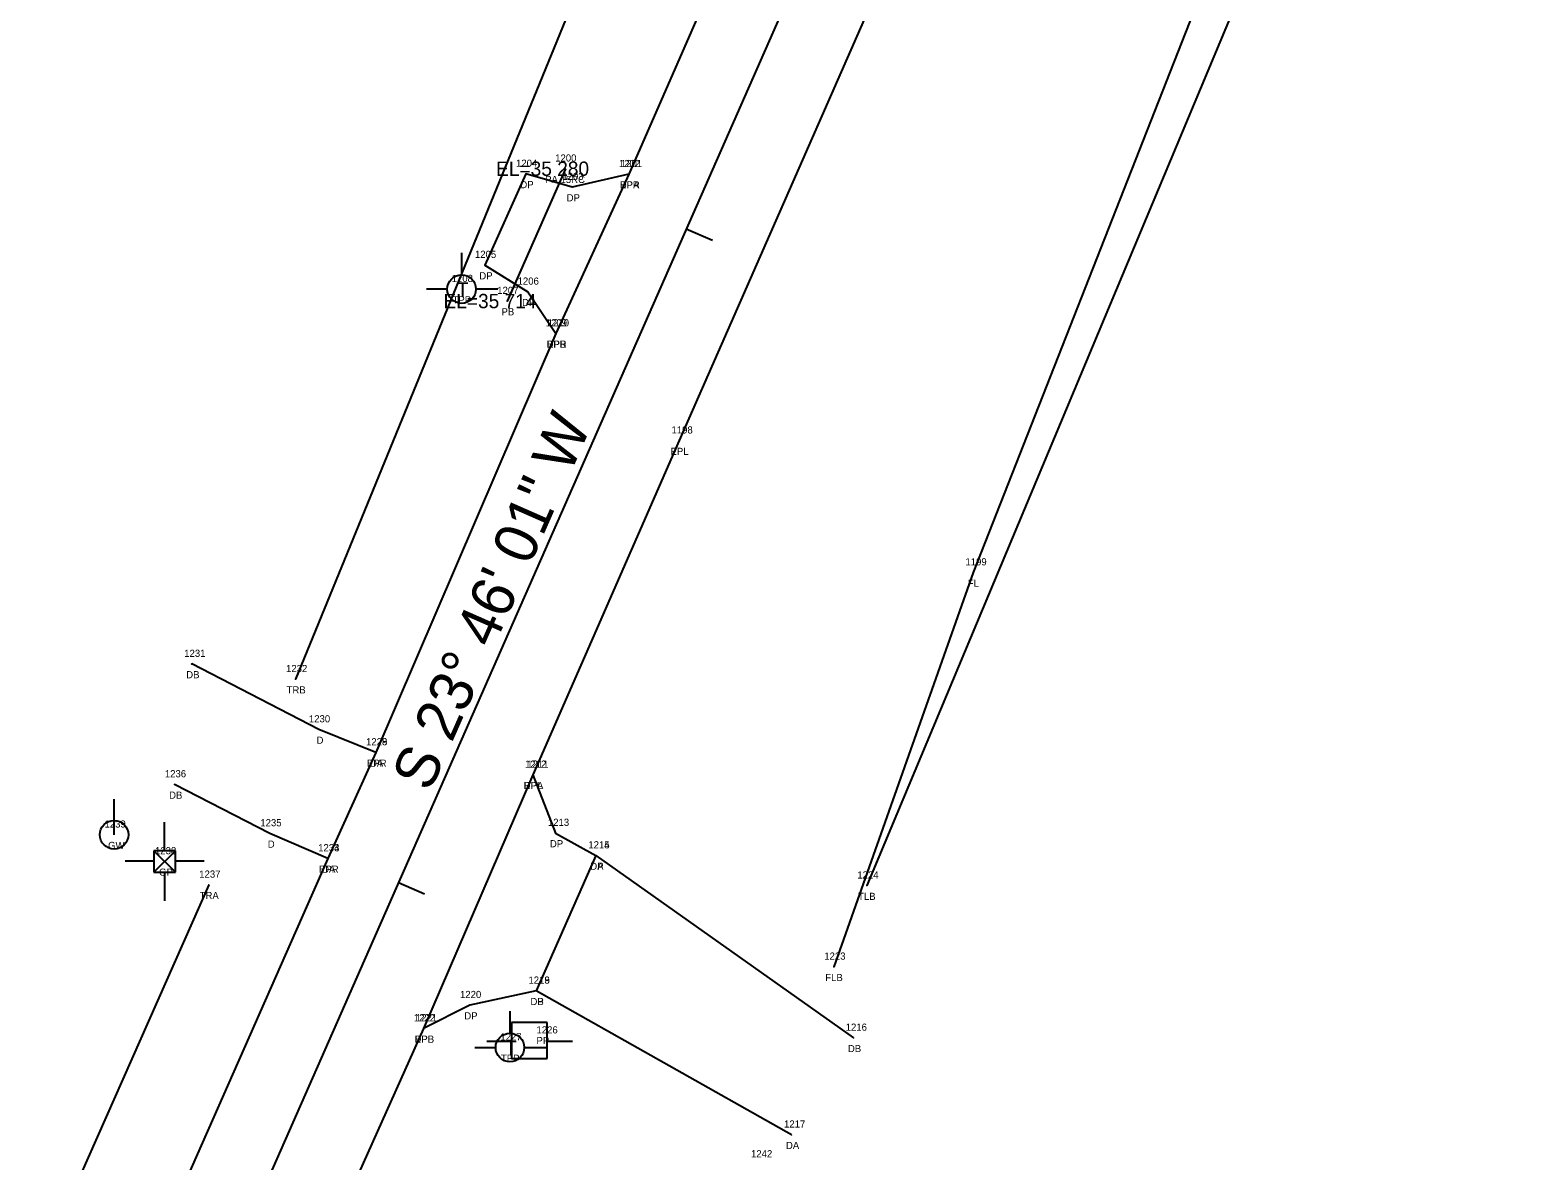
# Model space of a CAD drawing. Extents: x 2432632 to 2433497, y 684847 to 688233.
# Drawn here: x 2432817 to 2433028, y 685151.9 to 685310.2 of the extents above; entities that cross this region are included whole.
import ezdxf

# ---------------------------------------------------------------- set-up
doc = ezdxf.new("R2010")
doc.units = 0
for name, color, linetype in [('RD_EX_DR_Pipe', 7, 'Continuous'), ('RD_EX_DR_Pipe_txCode', 7, 'Continuous'), ('RD_EX_Driveway', 7, 'Continuous'), ('RD_EX_Driveway_txCode', 7, 'Continuous'), ('RD_EX_Fence_Other', 7, 'Continuous'), ('RD_EX_Fence_Other_txCode', 7, 'Continuous'), ('RD_EX_Road', 7, 'Continuous'), ('RD_EX_Road_txCode', 7, 'Continuous'), ('RD_EX_UT', 7, 'Continuous'), ('RD_EX_UT_txCode', 7, 'Continuous'), ('RD_EX_VEG', 7, 'Continuous'), ('RD_EX_VEG_txCode', 7, 'Continuous'), ('RD_HC_Cl', 7, 'Continuous'), ('RD_HC_Data', 7, 'Continuous'), ('RD_HC_Data_Tic', 7, 'Continuous'), ('RD_SMD_Locator', 7, 'Continuous'), ('RD_TX_Pipe_ElevEX', 7, 'Continuous')]:
    doc.layers.add(name, color=color, linetype=linetype)

msp = doc.modelspace()

# ---------------------------------------------------------------- linework, layer by layer
at = {"layer": 'RD_EX_DR_Pipe'}
msp.add_line((2432891.94, 685290.81), (2432883.78, 685272.28), dxfattribs=at)
at = {"layer": 'RD_EX_Driveway'}
for p, q in [((2432896.21, 685194.66), (2432932.26, 685169.13)), ((2432923.6, 685155.57), (2432887.83, 685175.72))]:
    msp.add_line(p, q, dxfattribs=at)
for points in [[(2432900.81, 685290.04), (2432892.9, 685288.24), (2432886.42, 685290.08), (2432880.67, 685277.32), (2432886.66, 685273.58), (2432890.58, 685267.74)], [(2432865.39, 685209.09), (2432857.42, 685212.3), (2432839.65, 685221.47)], [(2432887.37, 685205.96), (2432890.55, 685197.81), (2432896.21, 685194.66), (2432887.83, 685175.72), (2432878.57, 685173.71), (2432872.08, 685170.45)], [(2432858.68, 685194.25), (2432850.59, 685197.75), (2432837.25, 685204.61)]]:
    msp.add_lwpolyline(points, dxfattribs=at)
at = {"layer": 'RD_EX_Fence_Other'}
msp.add_lwpolyline([(2433123.26, 685650.94), (2433063.8, 685520.15), (2433021.44, 685418.51), (2432949, 685234.28), (2432929.52, 685179.08)], dxfattribs=at)
at = {"layer": 'RD_EX_Road'}
for points in [[(2433057.55, 685694.23), (2433042.27, 685641.38), (2433024.96, 685589.31), (2433008.78, 685545.65), (2432989.83, 685496.35), (2432969.04, 685447.03), (2432957.98, 685420.84), (2432946.33, 685394.97), (2432928.47, 685353.31), (2432900.81, 685290.04), (2432890.58, 685267.74), (2432865.39, 685209.09), (2432858.68, 685194.25), (2432808.1, 685079.72), (2432767.11, 684987)], [(2433077.66, 685687.92), (2433062.23, 685635.7), (2433044.84, 685582.68), (2433028.22, 685537.07), (2433009.68, 685489.83), (2432988.53, 685438.27), (2432948.62, 685345.62), (2432907.86, 685252.74), (2432887.37, 685205.96), (2432872.08, 685170.45), (2432827.85, 685071.69), (2432787.31, 684979.59)]]:
    msp.add_lwpolyline(points, dxfattribs=at)
at = {"layer": 'RD_EX_UT'}
for p, q in [((2432877.41, 685279.02), (2432877.41, 685275.95)), ((2432872.48, 685273.97), (2432875.41, 685273.97)), ((2432879.41, 685273.97), (2432882.48, 685273.97)), ((2432828.78, 685197.57), (2432828.78, 685202.57)), ((2432835.85, 685195.33), (2432835.85, 685199.33)), ((2432834.32, 685193.88), (2432830.32, 685193.88)), ((2432837.35, 685195.33), (2432834.35, 685192.33)), ((2432834.35, 685195.33), (2432837.35, 685192.33)), ((2432837.35, 685195.33), (2432834.35, 685195.33)), ((2432834.35, 685195.33), (2432834.35, 685192.33)), ((2432837.35, 685192.33), (2432837.35, 685195.33)), ((2432837.36, 685193.9), (2432841.38, 685193.9)), ((2432834.35, 685192.33), (2432837.35, 685192.33)), ((2432835.85, 685192.33), (2432835.85, 685188.33)), ((2432884.18, 685172.85), (2432884.18, 685169.78)), ((2432889.38, 685171.26), (2432884.38, 685171.26)), ((2432884.38, 685171.26), (2432884.38, 685166.26)), ((2432889.38, 685166.26), (2432889.38, 685171.26)), ((2432880.95, 685168.69), (2432884.41, 685168.69)), ((2432889.31, 685168.69), (2432892.95, 685168.69)), ((2432879.25, 685167.79), (2432882.18, 685167.79)), ((2432884.38, 685166.26), (2432889.38, 685166.26)), ((2432886.18, 685167.79), (2432889.25, 685167.79))]:
    msp.add_line(p, q, dxfattribs=at)
for centre in [(2432877.41, 685273.95), (2432828.78, 685197.57), (2432884.18, 685167.78)]:
    msp.add_circle(centre, 2, dxfattribs=at)
at = {"layer": 'RD_EX_VEG'}
msp.add_line((2432842.03, 685190.56), (2432754.62, 684993.17), dxfattribs=at)
for points in [[(2433137.8, 685665.13), (2433067, 685525.91), (2432991.08, 685326.61), (2432934.15, 685190.44)], [(2433025.22, 685647.63), (2432992.1, 685555.75), (2432950.65, 685455.04), (2432854.18, 685219.34)]]:
    msp.add_lwpolyline(points, dxfattribs=at)
at = {"layer": 'RD_HC_Cl'}
msp.add_line((2432993.64, 685474.92), (2432777.18, 684983.39), dxfattribs=at)
at = {"layer": 'RD_HC_Data_Tic'}
for p, q in [((2432908.86, 685282.41), (2432912.52, 685280.8)), ((2432868.56, 685190.89), (2432872.22, 685189.28))]:
    msp.add_line(p, q, dxfattribs=at)
at = {"layer": 'RD_SMD_Locator'}
for centre in [(2432891.94, 685290.81), (2432886.42, 685290.08), (2432892.9, 685288.24), (2432900.81, 685290.04), (2432900.81, 685290.04), (2432880.67, 685277.32), (2432886.66, 685273.58), (2432883.78, 685272.28), (2432890.58, 685267.74), (2432890.58, 685267.74), (2432907.86, 685252.74), (2432949, 685234.28), (2432839.65, 685221.47), (2432854.18, 685219.34), (2432857.42, 685212.3), (2432865.39, 685209.09), (2432865.39, 685209.09), (2432887.37, 685205.96), (2432887.37, 685205.96), (2432837.25, 685204.61), (2432850.59, 685197.75), (2432890.55, 685197.81), (2432858.68, 685194.25), (2432858.68, 685194.25), (2432896.21, 685194.66), (2432896.21, 685194.66), (2432842.03, 685190.56), (2432934.15, 685190.44), (2432929.52, 685179.08), (2432887.83, 685175.72), (2432887.83, 685175.72), (2432878.57, 685173.71), (2432872.08, 685170.45), (2432872.08, 685170.45), (2432932.26, 685169.13), (2432923.6, 685155.57)]:
    msp.add_circle(centre, 0.001, dxfattribs=at)

# ---------------------------------------------------------------- texts
at = {"layer": 'RD_EX_DR_Pipe_txCode'}
for s, p in [('1200', (2432890.51, 685291.81)), ('PA 15RC', (2432889.1, 685288.81)), ('1207', (2432882.4, 685273.28)), ('PB', (2432883, 685270.28))]:
    msp.add_text(s, height=1, dxfattribs=at).set_placement(p)
at = {"layer": 'RD_EX_Driveway_txCode'}
for s, p in [('1204', (2432885.03, 685291.08)), ('1202', (2432899.43, 685291.04)), ('DP', (2432885.64, 685288.08)), ('1203', (2432891.51, 685289.24)), ('DPA', (2432899.55, 685288.04)), ('DP', (2432892.12, 685286.24)), ('1205', (2432879.28, 685278.32)), ('DP', (2432879.89, 685275.32)), ('1206', (2432885.25, 685274.58)), ('DP', (2432885.88, 685271.58)), ('1209', (2432889.19, 685268.74)), ('DPB', (2432889.32, 685265.74)), ('1231', (2432838.59, 685222.47)), ('DB', (2432838.87, 685219.47)), ('1230', (2432856.04, 685213.3)), ('D', (2432857.11, 685210.3)), ('1229', (2432864.04, 685210.09)), ('DA', (2432864.59, 685207.09)), ('1236', (2432835.88, 685205.61)), ('1212', (2432886.3, 685206.96)), ('DPA', (2432886.1, 685203.96)), ('DB', (2432836.47, 685202.61)), ('1235', (2432849.24, 685198.75)), ('1213', (2432889.49, 685198.81)), ('D', (2432850.28, 685195.75)), ('1234', (2432857.34, 685195.25)), ('DP', (2432889.77, 685195.81)), ('1214', (2432895.15, 685195.66)), ('1215', (2432895.15, 685195.66)), ('DA', (2432895.42, 685192.66)), ('DP', (2432895.43, 685192.66)), ('DA', (2432857.89, 685192.25)), ('1218', (2432886.77, 685176.72)), ('1219', (2432886.77, 685176.72)), ('1220', (2432877.19, 685174.71)), ('DB', (2432887.05, 685173.72)), ('DP', (2432887.05, 685173.72)), ('1221', (2432871.01, 685171.45)), ('DP', (2432877.79, 685171.71)), ('1216', (2432931.17, 685170.13)), ('DPB', (2432870.82, 685168.45)), ('DB', (2432931.48, 685167.13)), ('1217', (2432922.54, 685156.57)), ('DA', (2432922.81, 685153.57))]:
    msp.add_text(s, height=1, dxfattribs=at).set_placement(p)
at = {"layer": 'RD_EX_Fence_Other_txCode'}
for s, p in [('1199', (2432947.93, 685235.28)), ('FL', (2432948.26, 685232.28)), ('1223', (2432928.17, 685180.08)), ('FLB', (2432928.31, 685177.08)), ('1242', (2432917.92, 685152.41))]:
    msp.add_text(s, height=1, dxfattribs=at).set_placement(p)
at = {"layer": 'RD_EX_Road_txCode'}
for s, p in [('1201', (2432899.71, 685291.04)), ('EPR', (2432899.59, 685288.04)), ('1210', (2432889.47, 685268.74)), ('EPR', (2432889.35, 685265.74)), ('1198', (2432906.79, 685253.74)), ('EPL', (2432906.65, 685250.74)), ('1228', (2432864.04, 685210.09)), ('EPR', (2432864.16, 685207.09)), ('1211', (2432886.59, 685206.96)), ('EPL', (2432886.16, 685203.96)), ('1233', (2432857.34, 685195.25)), ('EPR', (2432857.45, 685192.25)), ('1222', (2432870.73, 685171.45)), ('EPL', (2432870.87, 685168.45))]:
    msp.add_text(s, height=1, dxfattribs=at).set_placement(p)
at = {"layer": 'RD_EX_UT'}
for p in [(2432876.74, 685272.9), (2432883.51, 685166.73)]:
    msp.add_text('T', height=2, dxfattribs=at).set_placement(p)
at = {"layer": 'RD_EX_UT_txCode'}
for s, p in [('1208', (2432876.02, 685274.95)), ('TPP', (2432876.14, 685271.95)), ('1239', (2432827.43, 685198.57)), ('GW', (2432827.93, 685195.57)), ('1238', (2432834.5, 685194.83)), ('GP', (2432835.07, 685191.83)), ('1226', (2432887.89, 685169.75)), ('1227', (2432882.84, 685168.78)), ('PP', (2432887.89, 685168.25)), ('TPP', (2432882.91, 685165.78))]:
    msp.add_text(s, height=1, dxfattribs=at).set_placement(p)
at = {"layer": 'RD_EX_VEG_txCode'}
for s, p in [('1232', (2432852.84, 685220.34)), ('TRB', (2432852.92, 685217.34)), ('1237', (2432840.69, 685191.56)), ('1224', (2432932.8, 685191.44)), ('TRA', (2432840.75, 685188.56)), ('TLB', (2432932.9, 685188.44))]:
    msp.add_text(s, height=1, dxfattribs=at).set_placement(p)
at = {"layer": 'RD_HC_Data'}
msp.add_text('S 23%%d 46\' 01" W', height=6, rotation=66.2329, dxfattribs=at).set_placement((2432872.97, 685203.4))
at = {"layer": 'RD_TX_Pipe_ElevEX'}
for s, p in [('EL=35 280  ', (2432882.24, 685289.81)), ('EL=35 714  ', (2432874.88, 685271.28))]:
    msp.add_text(s, height=2, dxfattribs=at).set_placement(p)

doc.saveas('drawing.dxf')
